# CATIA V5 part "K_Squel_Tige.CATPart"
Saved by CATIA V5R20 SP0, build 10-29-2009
Part number: Squelette_tige
Publications: "Plan.3"
Bounding box of the stored display mesh (mm): x -62 to -38, y 169.401 to 196.271, z -180.312 to -129.401
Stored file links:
  G:\Khaled_CFAO_2011\ST2M\ST2M_GR2\plakomicki\Khaled\CAD_ThinkMOTION\K_Squel_Tige.CATPart
  G:\Khaled_CFAO_2011\ST2M\ST2M_GR2\plakomicki\Khaled\CAD_ThinkMOTION\K_Squelette.CATProduct
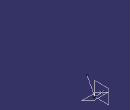
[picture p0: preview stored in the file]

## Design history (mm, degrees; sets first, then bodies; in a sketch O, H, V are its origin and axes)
Set1
  Plane1: linked copy from another document
  Point1: linked copy from another document
  Point2: linked copy from another document
Set2
  Plane2: type Offset, RefPlane Plane1, Offset -24
  Point3: type OnPlane, Support Plane2, RefPoint Point1, H 0, V 0, Direction (0, 1, 0)
  Line1: type PtPt, FirstPoint Point1, SecondPoint Point3
  Line2: type PtPt, FirstPoint Point1, SecondPoint Point2
  Plane3: type Normal, Curve Line2, RefPoint Point1
Body1 (main body)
